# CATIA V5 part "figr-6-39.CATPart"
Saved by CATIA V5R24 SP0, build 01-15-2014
Part number: Part1
Bounding box of the stored display mesh (mm): x -42.494 to 42.494, y -51.186 to 51.186, z 0 to 35
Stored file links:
  D:\KAVITA\CATIA V5-6R2014 Project_ Kavita\CATIA V5-6R2014_partfiles\Partfiles\c06_catia_v5-6r2014_prt\figr-6-39.CATPart
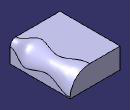
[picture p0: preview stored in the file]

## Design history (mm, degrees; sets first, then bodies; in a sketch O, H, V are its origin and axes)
Set1
  Point1: type OnCurve, Support edge [face of Pad1 | face of Pad1], Length 25.019
  Point2: type OnCurve, Support edge [face of Pad1 | face of Pad1], Length 63.062
Body1 (main body)
  Sketch1 on xy-plane, origin (0, 0, 0), H (1, 0, 0), V (0, 1, 0)
    line L1 (-42.4944, 51.1864) -> (42.4944, 51.1864)
    line L2 (42.4944, 51.1864) -> (42.4944, -51.1864)
    line L3 (42.4944, -51.1864) -> (-42.4944, -51.1864)
    line L4 (-42.4944, -51.1864) -> (-42.4944, 51.1864)
    axis line L5 (42.4944, -51.1864) -> (-42.4944, 51.1864)
    horizontal: L1 H, L3 H
    vertical: L2 V, L4 V
    midpoint: O L5
  Pad1: profile Sketch1, direction (0, 0, 1), length 35
  Fillet1: on edge [face of Pad1 | face of Pad1]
